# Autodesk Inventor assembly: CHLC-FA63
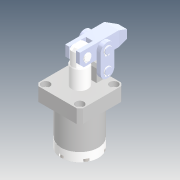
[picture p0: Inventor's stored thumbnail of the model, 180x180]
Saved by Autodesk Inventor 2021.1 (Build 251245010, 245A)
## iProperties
Created: 2019-04
Part Number: CHLC-FA63
Description: STEP AP214
Document SubType Name: Assembly
Designer: user
Title: CHLC-FA63¸Ü¸ËÊ½ÓÍÑ¹¸×.STEP
Revision Number: ÈÎºÎ
Sending System: SolidWorks 2016
Preprocessor: SwSTEP 2.0
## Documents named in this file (10)
- D:\Vault_2016\Projekty\Clamptek\Hydraulic\CHLC\CHLC-63\Inventor\CHLC-FA63\CHLC-FA63.iam
- D:\Vault_2016\Projekty\Clamptek\Hydraulic\CHLC\CHLC-63\Inventor\CHLC-FA63\CHLC-63-01.ipt
- D:\Vault_2016\Projekty\Clamptek\Hydraulic\CHLC\CHLC-63\Inventor\CHLC-FA63\CHLC-FA63±¾Ìå.ipt
- D:\Vault_2016\Projekty\Clamptek\Hydraulic\CHLC\CHLC-63\Inventor\CHLC-FA63\CHLC-FA63ºó¸Ç.ipt
- D:\Vault_2016\Projekty\Clamptek\Hydraulic\CHLC\CHLC-63\Inventor\CHLC-FA63\CHLC-63-03.ipt
- D:\Vault_2016\Projekty\Clamptek\Hydraulic\CHLC\CHLC-63\Inventor\CHLC-FA63\CHLC-63-04.ipt
- D:\Vault_2016\Projekty\Clamptek\Hydraulic\CHLC\CHLC-63\Inventor\CHLC-FA63\CHLC-63-05.ipt
- D:\Vault_2016\Projekty\Clamptek\Hydraulic\CHLC\CHLC-63\Inventor\CHLC-FA63\CHLC-63-02.ipt
- D:\Vault_2016\Projekty\Clamptek\Hydraulic\CHLC\CHLC-63\Inventor\CHLC-FA63\socket head cap screw_is_IS 2269 - M6 x 30-C.ipt
- D:\Vault_2016\Projekty\Clamptek\Hydraulic\CHLC\CHLC-63\Inventor\CHLC-FA63\CHLC-63-07.ipt
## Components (21 placed, 21 different names)
1. CHLC-63-01_1
2. CHLC-FA63±¾Ìå_2
3. CHLC-FA63ºó¸Ç_3
4. CHLC-63-03_4
5. CHLC-63-04_5
6. CHLC-63-04_6
7. CHLC-63-03_7
8. CHLC-63-05_8
9. CHLC-63-02_9
10. socket head cap screw_is_IS 2269 - M6 x 30-C_10
11. socket head cap screw_is_IS 2269 - M6 x 30-C_11
12. socket head cap screw_is_IS 2269 - M6 x 30-C_12
13. socket head cap screw_is_IS 2269 - M6 x 30-C_13
14. socket head cap screw_is_IS 2269 - M6 x 30-C_14
15. socket head cap screw_is_IS 2269 - M6 x 30-C_15
16. CHLC-63-07_16
17. CHLC-63-07_17
18. CHLC-63-07_18
19. CHLC-63-07_19
20. CHLC-63-07_20
21. CHLC-63-07_21
